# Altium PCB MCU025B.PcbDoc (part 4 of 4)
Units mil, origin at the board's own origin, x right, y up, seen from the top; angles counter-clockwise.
Board outline 2300 x 6150 mil, 6 copper layers (Top Signal, GND, Middle Signal, PWR, GND2, Bottom Signal), stack 61.64 mil thick; 237 components, 197 nets, 910 pads, 404 vias.
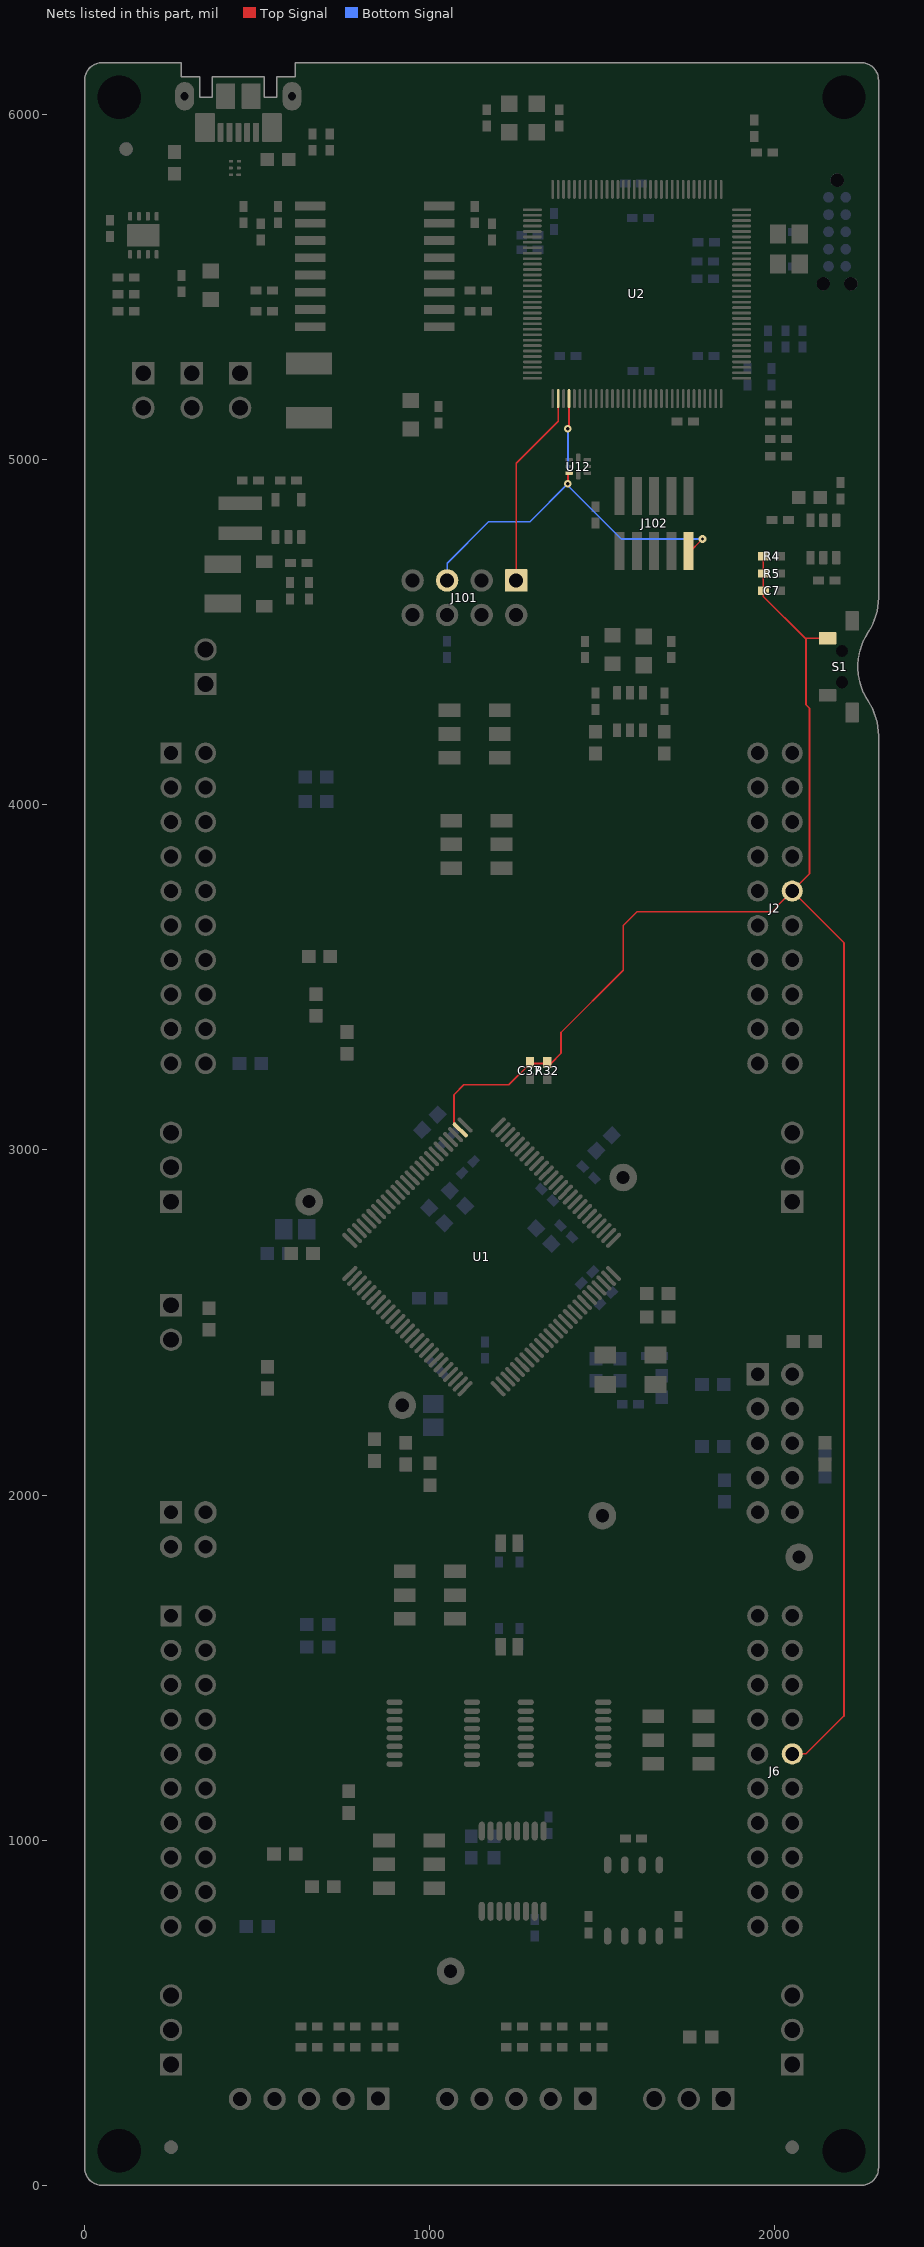
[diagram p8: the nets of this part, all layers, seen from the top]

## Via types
v1: diameter 22, hole 10, Top Signal to Bottom Signal, tented both sides, 400 vias
v2: diameter 19.68, hole 7.87, Top Signal to Bottom Signal, 4 vias

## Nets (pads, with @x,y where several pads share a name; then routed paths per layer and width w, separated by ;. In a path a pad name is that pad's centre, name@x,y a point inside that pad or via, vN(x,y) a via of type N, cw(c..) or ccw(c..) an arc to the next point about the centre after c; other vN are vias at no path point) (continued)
XDS_TMS_SWDIO: J101.5 J102.2 U2.36 U12.7 | length 1289.5
  Top Signal w5: v1(1400,4930) U12.7@1400,4960 ; v1(1400,5090) 1403.15,5093.15 U2.36@1403.15,5176.85 ; U12.7@1403.43,4960 U12.7@1403.43,4960.31 ; J102.2@1750,4730 v1(1790,4770)
  Bottom Signal w5: J101.5@1050,4650 1050,4700 1170,4820 1290,4820 v1(1400,4930) ; v1(1400,5090) v1(1400,4930) ; v1(1790,4770) 1555,4770 1400,4925 v1(1400,4930)
XDS_TXD: J101.1 U2.34 | length 577.2
  Top Signal w5: J101.1@1250,4650 1250,4990 1371.65,5111.65 U2.34@1371.65,5176.85
XRSn: C7.1 C37.2 J2.16 J6.16 R4.1 R5.2 R32.1 S1.4 U1.2 | length 5190.1
  Top Signal w5: U1.2@1088.06,3058.17 1070,3076.23 1070,3160 1098.5,3188.5 1228.5,3188.5 1290,3250 1350,3250 1380,3280 1380,3340 1560,3520 1560,3650 1600,3690 1990,3690 J2.16@2050,3750 ; C7.1@1966.38,4620 1966.38,4603.62 2087.32,4482.68 S1.4@2152.44,4482.68 ; C7.1@1966.38,4626.38 R5.2@1966.38,4670 ; R5.2@1966.38,4673.62 R4.1@1966.38,4720 ; J6.16@2050,1250 2090,1250 2200,1360 2200,3600 J2.16@2050,3750 ; 2090,4480 2090,4290 2100,4280 2100,3800 J2.16@2050,3750
pads on no net: FID1.1 FID2.1 FID3.1 FID4.1 FID5.1 FID6.1 J1.5 J2.17 J2.18 J5.9 J5.10 J6.17 J6.18 J10.7 J10.MH1 J10.MH2 J10.MH3 J11.9 J102.7 M1.0 M2.0 M3.0 M4.0 M5.0 M6.0 M7.0 M8.0 M9.0 MH1.1 MH2.1 MH3.1 MH4.1 S1. U1.43 U1.48 U1.49 U2.1 U2.2 U2.5 U2.6 U2.11 U2.12 U2.13 U2.14 U2.15 U2.18 U2.19 U2.20 U2.21 U2.22 U2.23 U2.24 U2.25 U2.27 U2.29 U2.30 U2.31 U2.32 U2.41 U2.42 U2.43 U2.44 U2.45 U2.46 U2.49 U2.50 U2.53 U2.54 U2.56 U2.57 U2.65 U2.67 U2.71 U2.72 U2.73 U2.74 U2.75 U2.76 U2.77 U2.78 U2.81 U2.82 U2.83 U2.84 U2.85 U2.86 U2.91 U2.92 U2.95 U2.102 U2.103 U2.104 U2.105 U2.106 U2.107 U2.108 U2.109 U2.110 U2.111 U2.112 U2.116 U2.117 U2.118 U2.119 U2.120 U2.121 U2.123 U2.124 U2.125 U2.126 U2.127 U2.128 U12.1 U101.7 U101.9@145.2,5650 U101.9@194.8,5650

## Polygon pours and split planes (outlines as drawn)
GND on GND "GND_GND_P018" (solid, remove dead copper, pour order 18): 865,6150 2300,6150 2300,0 0,0 0,5175 745,5175 865,5295
USB_GND on GND "GND_USB_GND_P000" (solid, remove dead copper, pour order 0): 0,5225 725,5225 815,5315 815,6150 0,6150
NetR23_1 on GND "GND_NETR23_1_P017" (solid, remove dead copper, pour order 17): 560,3300 600,3260 600,3030 860,2770 970,2880 970,2900 810,3060 810,3610 760,3660 760,4090 740,4110 580,4110 560,4090 560,3660 500,3600 320,3600 300,3580 300,3330 330,3300
NetR24_1 on GND "GND_NETR24_1_P016" (solid, remove dead copper, pour order 16): 580,1320 580,1120 560,1100 320,1100 300,1080 300,1030 300,826.67 322.86,800 700,800 800,900 800,1100 800,2450 900,2550 900,2560 820,2640 780,2640 592.5,2452.5 580,2440 580,1780
VDDA on PWR "PWR_VDDA_P014" (solid, remove dead copper, pour order 14): 977.73,3086.71 974.44,3090 869.17,3090.86 620,2850 620,2670 975,2315 1060,2400 1060,2690 1130,2760 1130,2900 1080,2950 1080,2980 1050,3020
VDD on PWR "PWR_VDD_P012" (solid, remove dead copper, pour order 12): 1555,2585 1555,2540 1530,2515 1485,2515 1270,2300 1160,2300 1111.41,2341.65 1110,2343.06 1110,2380 1170,2440 1170,2470 1260,2560 1400,2560 1470,2630 1470,2770 1190,3050 1140,3050 1080,2990 990,3080 990,3100 1040,3150 1340,3150 1580,2910 1580,2610
VDDIO on PWR "PWR_VDDIO_P010" (solid, remove dead copper, pour order 10): 870,2230 890,2210 1070,2210 1130,2270 1130,2400 1180,2440 1180,2470 1260,2550 1400,2550 1480,2630 1480,2770 1190,3060 1140,3060 1070,2990 1070,2940 1110,2900 1110,2750 1100,2750 1050,2700 1050,2410 950,2310 880,2310 870,2300
USB_VBUS on PWR "PWR_USB_VBUS_P002" (solid, remove dead copper, pour order 2): 0,6150 815,6150 815,5315 725,5225 0,5225
+3V3 on PWR "PWR_+3V3_P022" (solid, remove dead copper, pour order 22): 2300,6150 865,6150 865,5295 745,5175 0,5175 0,110 -10,100 2300,100
NetC59_1 on PWR "PWR_NETC59_1_P021" (solid, remove dead copper, pour order 21): 1840,5615 1665,5790 1645,5810 1560,5810 1550,5810 1510,5770 1510,5720 1720,5510 1880,5510 1910,5540 1910,5595 1890,5615
NetC106_2 on Top Signal "TOP_SIGNAL_NETC106_2_P030" (solid, remove dead copper, pour order 30): 730,5660 730,5505 485,5505 460,5530 460,5660
USB_VCC on Top Signal "TOP_SIGNAL_USB_VCC_P028" (solid, remove dead copper, pour order 28): 220,5220 250,5250 250,5385 325,5460 325,5715 240,5800 110,5800 50,5740 50,5280 110,5220
+3V3 on Top Signal "TOP_SIGNAL_+3V3_P027" (solid, remove dead copper, pour order 27): 480,4960 480,4930 460,4910 380,4910 380,4900 370,4890 370,4840 560,4840 590,4870 590,4960
NetD1_2 on Top Signal "TOP_SIGNAL_NETD1_2_P026" (solid, remove dead copper, pour order 26): 370,4830 550,4830 560,4820 560,4670 550,4660 460,4660 370,4750
NetC3_2 on Top Signal "TOP_SIGNAL_NETC3_2_P025" (solid, remove dead copper, pour order 25): 680,4730 660,4750 660,4755 660,4790 650,4800 605,4800 605,4705 560,4671.25 560,4630 680,4630
NetC3_1 on Top Signal "TOP_SIGNAL_NETC3_1_P024" (solid, remove dead copper, pour order 24): 325,4625 660,4625 660,4530 550,4530 420,4400 300,4400 280,4420 280,4580
+5V0 on Bottom Signal "BOTTOM_SIGNAL_+5V0_P020" (solid, remove dead copper, pour order 20): 865,6150 865,5295 745,5175 0,5175 0,0 1550,0 1550,850 1490,900 500,900 400,1000 400,4990 470,5060 800,5060 1000,5260 1000,5900 1100,6000 2000,6000 2050,6050 2050,6150
GND on GND2 "GND2_GND_P029" (solid, remove dead copper, pour order 29): 865,6160 865,5295 745,5175 -20,5175 -20,0 2320,0 2320,6160

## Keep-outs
Keep-Out Layer:
  text ".Layer_Name" at 577,-858.49 h60

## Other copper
Top Signal:
  text ".Layer_Name" at 577,-858.49 h60
GND:
  text ".Layer_Name" at 580,-860 h60
PWR:
  text ".Layer_Name" at 580,-860 h60
Middle Signal:
  text ".Layer_Name" at 580,-860 h60
GND2:
  text ".Layer_Name" at 580,-860 h60
Bottom Signal:
  text ".Layer_Name" at 577,-858.49 h60

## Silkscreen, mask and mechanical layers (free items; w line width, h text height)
Top Overlay:
  drawing of 9484 lines, arcs and shapes, not listed
  text "+3V3" at 110,5050 h30
  text "+5V0" at 250,5050 h30
  text "GND" at 410,5050 h30
  text "XDS110 Out" at 1520,4990 h30
  text "TCK" at 940,4480 h30 r270
  text "TMS" at 1040,4480 h30 r270
  text "TXD<<" at 1140,4480 h30 r270
  text "RXD>>" at 1240,4480 h30 r270
  text "XRSn" at 1980,4365 h72.83
  text "+5V0 / From Boost" at 420,4300 h30
  text "28/29" at 865.03,4260 h30
  text "UART / SELECT" at 1245,4180 h30
  text "35/37" at 865.03,4130 h30
  text "40" at 1830,4130 h30
  text "39" at 1830,4035 h30
  text "2" at 150,4030 h30
  text "19" at 2120,4030 h30
  text "BP" at 955,3940 h30
  text "38" at 1830,3935 h30
  text "3" at 150,3930 h30
  text "23" at 420,3930 h30
  text "18" at 2120,3930 h30
  text "28/29 / ROUTE" at 1255,3860 h30
  text "4" at 150,3830 h30
  text "24" at 420,3830 h30
  text "37" at 1830,3830 h30
  text "17" at 2120,3830 h30
  text "UART" at 895.02,3800 h30
  text "5" at 150,3730 h30
  text "25" at 420,3730 h30
  text "36" at 1830,3730 h30
  text "16" at 2120,3730 h30
  text "6" at 150,3630 h30
  text "26" at 420,3630 h30
  text "35" at 1830,3630 h30
  text "15" at 2120,3630 h30
  text "7" at 150,3530 h30
  text "27" at 420,3530 h30
  text "34" at 1830,3530 h30
  text "14" at 2120,3530 h30
  text "LAUNCHXL-F280049C" at 825,3450 h50
  text "8" at 150,3430 h30
  text "28" at 420,3430 h30
  text "33" at 1830,3430 h30
  text "13" at 2120,3430 h30
  text "9" at 150,3330 h30
  text "29" at 420,3330 h30
  text "32" at 1830,3330 h30
  text "12" at 2120,3330 h30
  text "30" at 420,3240 h30
  text "10" at 130,3230 h30
  text "31" at 1830,3230 h30
  text "11" at 2120,3230 h30
  text "VDD" at 1620,2900 h30
  text "VDDA" at 480,2840 h30
  text "VREFHI" at 20,2530 h30
  text "FSI" at 1915,2405 h30
  text "RXCLK" at 1719.98,2325 h30
  text "TXCLK" at 2109,2325 h30
  text "VDDIO" at 720,2240 h30
  text "TXD0" at 2176,2130 h30
  text "RXD0" at 1720,2100 h30
  text "RXD1" at 1765,2025 h30
  text "TXD1" at 2179,2025 h30
  text "+3V3" at 1560,1920 h30
  text "24" at 1120,1875 h30
  text "32" at 1290,1875 h30
  text "+3V3 / TO / J5" at 60,1820 h30
  text "+5V0 / TO / J7" at 420,1820 h30
  text "GND" at 2135,1805 h30
  text "1" at 1335,1800 h30
  text "ALT" at 800,1770 h30
  text "BOOT" at 1330,1700 h30
  text "80" at 1830,1635 h30
  text "BP" at 820,1630 h30
  text "0" at 1335,1595 h30
  text "42" at 130,1530 h30
  text "79" at 1830,1530 h30
  text "59" at 2120,1530 h30
  text "35/37 / ROUTE" at 920,1490 h30
  text "43" at 130,1430 h30
  text "63" at 420,1430 h30
  text "78" at 1830,1430 h30
  text "58" at 2120,1430 h30
  text "ALT" at 1570,1420 h30 r270
  text "44" at 130,1330 h30
  text "64" at 420,1330 h30
  text "77" at 1830,1330 h30
  text "57" at 2120,1330 h30
  text "BP" at 1570,1235 h30 r270
  text "45" at 130,1230 h30
  text "65" at 420,1230 h30
  text "76" at 1830,1230 h30
  text "56" at 2120,1230 h30
  text "46" at 130,1130 h30
  text "66" at 420,1130 h30
  text "75" at 1840,1130 h30
  text "55" at 2120,1130 h30
  text "CAN / ROUTE" at 1650,1070 h30
  text "47" at 130,1030 h30
  text "67" at 420,1030 h30
  text "74" at 1840,1030 h30
  text "54" at 2120,1030 h30
  text "BP" at 770,980 h25
  text "BP" at 1060,980 h25
  text "48" at 130,930 h30
  text "68" at 420,930 h30
  text "73" at 1830,930 h30
  text "53" at 2120,930 h30
  text "Q1" at 780,915 h25
  text "Q2" at 1060,915 h25
  text "J12" at 760,840 h25
  text "J13" at 1050,840 h25
  text "49" at 130,830 h30
  text "69" at 420,830 h30
  text "72" at 1830,830 h30
  text "52" at 2120,830 h30
  text "QEP Select" at 805,775 h30
  text "50" at 130,730 h30
  text "70" at 420,730 h30
  text "71" at 1840,730 h30
  text "51" at 2120,730 h30
  text "+5V0" at 900,640 h30
  text "EQEP2" at 600,315 h30
  text "EQEP1" at 1195,315 h30
  text "CAN" at 1735,315 h30
  text "GND" at 440,180 h30 r270
  text "+5V0" at 540,180 h30 r270
  text "2I" at 640,180 h30 r270
  text "2B" at 740,180 h30 r270
  text "2A" at 840,180 h30 r270
  text "GND" at 1040,180 h30 r270
  text "+5V0" at 1140,180 h30 r270
  text "1I" at 1240,180 h30 r270
  text "1B" at 1340,180 h30 r270
  text "1A" at 1440,180 h30 r270
  text "GND" at 1630,180 h30 r270
  text "CANL" at 1730,180 h30 r270
  text "CANH" at 1830,180 h30 r270
  text ".Layer_Name" at 577,-858.49 h60
Bottom Overlay:
  drawing of 12860 lines, arcs and shapes, not listed
  text "www.ti.com/launchpad" at 1140,4705 h100
  text "LAUNCHXL-F280049C / Development Kit" at 2300,4705 h100
  text "1" at 260,4220 h30
  text "21" at 370,4220 h30
  text "J3" at 470,4220 h40
  text "J4" at 1900,4220 h40
  text "40" at 1980,4220 h30
  text "20" at 2080,4220 h30
  text "P10" at 1880,4130 h30
  text "P11" at 1880,4035 h30
  text "PGAGND" at 180,4030 h30
  text "P57" at 2200,4030 h30
  text "P08" at 1880,3935 h30
  text "NC" at 2175,3935 h30
  text "P13" at 180,3930 h30
  text "AA5" at 500,3930 h30
  text "P40" at 180,3830 h30
  text "AB0" at 500,3830 h30
  text "P09" at 1880,3830 h30
  text "NC" at 2170,3830 h30
  text "'.PRJ_Number'.PCB_Rev" at 1370,3800 h108.27
  text "NC" at 180,3730 h30
  text "AC2" at 500,3730 h30
  text "P04" at 1880,3730 h30
  text "XRSn" at 2230,3730 h30
  text "AB3" at 180,3630 h30
  text "AB1" at 500,3630 h30
  text "P05" at 1880,3630 h30
  text "P16" at 2200,3630 h30
  text "AB2/G1I" at 570,3540 h25
  text "P56" at 180,3530 h30
  text "P58" at 1880,3530 h30
  text "P17" at 2200,3530 h30
  text "AC0/G3I" at 575,3435 h25
  text "AC4" at 180,3430 h30
  text "P30" at 1880,3430 h30
  text "P39" at 2200,3430 h30
  text "AA9/G5I" at 575,3340 h25
  text "P37" at 180,3330 h30
  text "P18" at 1880,3330 h30
  text "P23" at 2200,3330 h30
  text "P35" at 180,3230 h30
  text "P25" at 1880,3230 h30
  text "P59" at 2200,3230 h30
  text "AA1/DACB" at 640,3180 h30
  text "10" at 270,3150 h30
  text "30" at 380,3150 h30
  text "31" at 1970,3150 h30
  text "11" at 2070,3150 h30
  text "41" at 280,1720 h30
  text "61" at 370,1720 h30
  text "J7" at 470,1720 h40
  text "J8" at 1900,1720 h40
  text "80" at 1970,1720 h30
  text "60" at 2080,1720 h30
  text "P00" at 1880,1635 h30
  text "PGAGND" at 175,1530 h30
  text "P01" at 1880,1530 h30
  text "P27" at 2200,1530 h30
  text "P28" at 175,1430 h30
  text "AA6" at 500,1430 h30
  text "P06" at 1875,1430 h30
  text "NC" at 2170,1430 h30
  text "P29" at 175,1330 h30
  text "AB6" at 500,1330 h30
  text "NC" at 2170,1330 h30
  text "P07" at 1880,1325 h30
  text "AB4/G4O" at 180,1240 h25
  text "AC14" at 525,1230 h30
  text "P02" at 1880,1230 h30
  text "XRSn" at 2230,1230 h30
  text "AA4/G2O" at 180,1135 h25
  text "AC1" at 490,1130 h30
  text "P03" at 1880,1130 h30
  text "P24" at 2200,1130 h30
  text "AC3/G4I" at 575,1035 h25
  text "P22" at 180,1030 h30
  text "P26" at 1880,1030 h30
  text "P31" at 2200,1030 h30
  text "AA8/G6O" at 180,935 h25
  text "P15" at 1880,930 h30
  text "P33" at 2200,930 h30
  text "AC5/G6I" at 575,895 h25
  text "AA3/G2I" at 575,835 h25
  text "NC" at 180,830 h30
  text "P14" at 1880,830 h30
  text "P34" at 2200,830 h30
  text "NC" at 180,730 h30
  text "P32" at 1880,730 h30
  text "P12" at 2200,730 h30
  text "AA0/DACA" at 650,680 h30
  text "71" at 1970,650 h30
  text "51" at 2070,650 h30
  text "50" at 270,640 h30
  text "70" at 370,640 h30
  text ".Layer_Name" at 577,-858.49 h60
Top Paste:
  text ".Layer_Name" at 577,-858.49 h60
Bottom Paste:
  text ".Layer_Name" at 577,-858.49 h60
Top Solder:
  text ".Layer_Name" at 577,-858.49 h60
  text ".Layer_Name" at 577,-858.49 h60
Bottom Solder:
  text ".Layer_Name" at 577,-858.49 h60
Drill Guide:
  text ".Layer_Name" at 577,-858.49 h60
M1 Board Outline:
  the board outline again, w10
  text ".Layer_Name" at 577,-858.49 h60
M2 Board Dimensions:
  rectangle: 125,-400 500,-275
  rectangle: 0,-275 125,-150
  lines w7: 0,-275 1000,-275 ; 125,-400 125,-150 ; 250,-400 250,-150 ; 500,-400 500,-150 ; 750,-400 750,-150 ; 0,-400 0,-150 1000,-150 1000,-400 0,-400
  text "Radius 50 mil, 4 corners" at 2406,-202 h100
  text ".Layer_Name" at 577,-858.49 h60
M3 3D STEP Top:
  text ".Layer_Name" at 577,-858.49 h60
M4 3D STEP Bottom:
  text ".Layer_Name" at 577,-858.49 h60
M5 Assembly Top:
  lines w10: -292,-930.17 6308,-930.17 ; -292,-726.83 6310,-726.83 ; -292,-523.5 -292,-1133.5 3713,-1133.5 6310,-1133.5 6310,-523.5 -291.5,-523.5 -291.5,-1133.5 1284,-1133.5 ; 2173,-1133.5 2173,-523.5 ; 3440,-726.83 3440,-523.5 ; 4280,-726.83 4280,-523.5 ; 4902,-1140 4902,-937.17
  text "Place all Shunts (9 total) as described  in Figure 1 of Test Procedure." at 140,6720 h40
  text "Ensure that all switches are placed in the proper direction with default positions as described in Figure 1 of Test Procedure" at 140,6620 h40
  text "COMPONENTS MARKED 'DNP' SHOULD NOT BE POPULATED." at 1153.5,-318.5 h60
  text "ASSEMBLY VARIANT:" at 1153,-434 h60
  text ".VariantName" at 2189,-434 h60
  text "PCB VIEWED FROM TOP SIDE" at -228.5,-655.67 h60
  text "BOARD #:" at 2248,-655.67 h60
  text ".PRJ_Number" at 2793.5,-655.67 h60
  text "REV:" at 3638,-655.67 h60
  text ".PCB_Rev" at 3929.5,-655.67 h60
  text "SVN REV:" at 4476,-655.67 h60
  text ".VersionControl_RevNumber" at 4982,-655.67 h60
  text "TID #:" at 2248,-859 h60
  text ".TID" at 2793.5,-859 h60
  text ".Layer_Name" at 580,-860 h60
  text "PLOT NAME =" at -228.5,-1064.34 h60
  text ".plot_File_Name" at 577,-1064.34 h60
  text "GENERATED    :" at 2250,-1064.34 h60
  text ".Print_Date" at 3119.5,-1064.34 h60
  text ".Print_Time" at 3848.5,-1064.34 h60
  text "TEXAS INSTRUMENTS" at 5113,-1064.34 h60
M6 Assembly Bottom:
  lines w10: -292.5,-727.33 6309.5,-727.33 ; -290.5,-930.67 6309.5,-930.67 ; 1115.5,-1140.5 1115.5,-937.67 ; 1737.5,-727.33 1737.5,-524 ; 2577.5,-727.33 2577.5,-524 ; 3844.5,-1134 3844.5,-524 ; 4733.5,-1134 6309,-1134 6309,-524 -292.5,-524 -292.5,-1134 2304.5,-1134 6309.5,-1134 6309.5,-524
  text "COMPONENTS MARKED 'DNP' SHOULD NOT BE POPULATED." at 6102,-318 h60
  text ".VariantName" at 5058,-434 h60
  text "ASSEMBLY VARIANT:" at 6097,-434 h60
  text ".VersionControl_RevNumber" at 1035.5,-656.17 h60
  text "SVN REV:" at 1541.5,-656.17 h60
  text ".PCB_Rev" at 2088,-656.17 h60
  text "REV:" at 2379.5,-656.17 h60
  text ".PRJ_Number" at 3224,-656.17 h60
  text "BOARD #:" at 3769.5,-656.17 h60
  text "PCB VIEWED FROM BOTTOM SIDE" at 6246,-656.17 h60
  text ".Layer_Name" at 580,-860 h60
  text ".TID" at 3224,-859.5 h60
  text "TID #:" at 3769.5,-859.5 h60
  text "TEXAS INSTRUMENTS" at 904.5,-1064.84 h60
  text ".Print_Time" at 2169,-1064.84 h60
  text ".Print_Date" at 2898,-1064.84 h60
  text "GENERATED    :" at 3767.5,-1064.84 h60
  text ".plot_File_Name" at 5440.5,-1064.84 h60
  text "PLOT NAME =" at 6246,-1064.84 h60
M7 LPKF Text Top:
  text ".Layer_Name" at 580,-860 h60
M8 LPKF Text Bottom:
  text ".Layer_Name" at 580,-860 h60
M9 Title Sheet:
  drawing of 57 lines, arcs and shapes, not listed
  text "1" at 739.84,8036.5 h70
  text "2" at 3235.5,8036.5 h70
  text "3" at 5724.84,8036.5 h70
  text "4" at 8231.51,8036.5 h70
  text "5" at 10730.5,8036.5 h70
  text "6" at 13235.5,8036.5 h70
  text "A" at -416.5,6893.5 h70
  text "A" at 14383.5,6893.5 h70
  text "B" at -416.5,4513.5 h70
  text "B" at 14383.5,4513.5 h70
  text "C" at -416.5,2138.5 h70
  text "C" at 14383.5,2138.5 h70
  text "PROJECT TITLE:" at 11343.5,277.5 h45
  text ".PRJ_Title" at 11393.5,144.17 h70
  text "DESIGNED FOR:" at 11343.5,-23.5 h45
  text ".PRJ_Customer" at 11393.5,-163.5 h70
  text "D" at -416.5,-231.5 h70
  text "D" at 14383.5,-231.5 h70
  text "FILE NAME:" at 11343.5,-323.5 h45
  text ".PCB_File_Name_No_Path" at 11393.5,-443.5 h70
  text "Texas Instruments (TI) and/or its licensors do not warrant the accuracy or completeness of this specification" at 6374,-605.34 h45
  text "ENGINEER:" at 11343.5,-613.5 h45
  text "LAYOUT BY:" at 12848.5,-613.5 h45
  text "or any information contained therein. TI and/or its licensors do not warrant that this design will meet" at 6329.01,-718 h45
  text ".PRJ_Engineer" at 11393.5,-768.49 h70
  text ".PCB_Layout" at 12899,-768.49 h70
  text "the specifications, will be suitable for your application or fit for any particular purpose, or will operate in" at 6329.01,-830.67 h45
  text ".Layer_Name" at 577,-858.49 h60
  text "ALTIUM DESIGNER VERSION:" at 12848.5,-923.5 h45
  text "an implementation. TI and/or its licensors do not warrant that the design is production worthy. You should" at 6329.01,-943.33 h45
  text "completely validate and test your design implementation to confirm the system functionality for your application." at 6374,-1056 h45
  text ".print_Scale" at 11393.5,-1056.83 h70
  text ".Application_BuildNumber" at 12899,-1056.83 h70
  text "1" at 739.84,-1263.5 h70
  text "2" at 3235.5,-1263.5 h70
  text "3" at 5724.84,-1263.5 h70
  text "4" at 8231.51,-1263.5 h70
  text "5" at 10730.5,-1263.5 h70
  text "6" at 13235.5,-1263.5 h70
M10 Fab Notes:
  drawing of 189 lines, arcs and shapes, not listed
  text "DESIGN INFORMATION" at 12382.02,6356.17 h60
  text "MIN. TRACK WIDTH:" at 11737.46,6224.05 h60
  text "5" at 12833.7,6224.05 h60
  text "MIL" at 12988.46,6224.05 h60
  text "MIN. CLEARANCE:" at 11737.46,6099.92 h60
  text "0.2" at 12773.7,6099.93 h60
  text "mm" at 12988.46,6099.92 h60
  text "MIN. VIA PAD SIZE:" at 11737.46,5975.8 h60
  text "24" at 12803.71,5975.8 h60
  text "MIL" at 12988.46,5975.8 h60
  text "0.05mm (2MIL)" at 12432.46,5845.9 h60
  text "MINIMUM ANNULAR RING" at 11408.23,5837.67 h60
  text "EXTERNAL" at 13140.46,5837.67 h60
  text "PER" at 11608.23,5727.55 h60
  text "IPC-D-275 CLASS 2 LEVEL C" at 11828.23,5727.54 h60
  text "MIL, HOLES" at 13316.46,5627.07 h60
  text "+/-" at 12924,5618.48 h60
  text "+/-" at 13778,5618.48 h60
  text "REGISTRATION TOLERANCES:" at 11408.23,5617.42 h60
  text "METAL" at 12608,5617.42 h60
  text "5" at 13184.2,5617.42 h60
  text "3" at 14017.2,5617.42 h60
  text "MIL" at 14133.46,5617.42 h60
  text "HOLE SIZE TOLERANCE (UNLESS OTHERWISE SPECIFIED):" at 11408.23,5519.1 h60
  text "+/-" at 13778,5516.23 h60
  text "5" at 14017.2,5515.17 h60
  text "MIL" at 14133.46,5515.17 h60
  text "MATERIAL:" at 11333.46,5377.52 h60
  text "FR-4 High Tg" at 12319.9,5249 h60
  text "X" at 12175.46,5241.01 h60
  text "FR-408" at 11754.46,5236.49 h60
  text "OTHER" at 13242.46,5236.49 h60
  text "62 MIL (1.6mm) +/-10%" at 12074.56,5093.46 h60
  text "X" at 11954.46,5091.01 h60
  text "THICKNESS:" at 11408.23,5085.24 h60
  text "OTHER" at 13359.46,5085.24 h60
  text "TOLERANCE:" at 11408.23,4946.92 h60
  text "ANSI IPC-6012 TYPE 3 CLASS 2" at 12434.48,4946.92 h60
  text "IPC-A600" at 13120,4820 h72.83
  text "OTHER +/-" at 12434.46,4802.73 h60
  text "X" at 12265,4800 h60
  text "BOW & TWIST:" at 11408.23,4657.54 h60
  text "ANSI IPC-6012 TYPE 3 CLASS 2" at 12434.48,4657.54 h60
  text "X" at 12255,4535 h60
  text "IPC-A600" at 13120,4515 h72.83
  text "OTHER +/-" at 12434.46,4510.85 h60
  text "DRILLING:" at 11333.46,4380.23 h60
  text "NC_DRILL FILES" at 13094.46,4275.04 h60
  text "REFERENCE:" at 11408.23,4271.1 h60
  text "X" at 12065.46,4271.01 h60
  text "AS SHOWN" at 12243.46,4271.1 h60
  text "X" at 12966.46,4271.1 h60
  text "OTHER" at 13392.46,4128.85 h60
  text "PTH COPPER THICKNESS:" at 11407.91,4125.32 h60
  text "X" at 12547.14,4125.32 h60
  text "20-30 um" at 12675.14,4125.32 h60
  text "BOARD FINISH:" at 11333.46,3977.73 h60
  text "SILKSCREEN:" at 11488.68,3867.6 h60
  text "X" at 12446.46,3867.6 h60
  text "TOP" at 12563.46,3867.6 h60
  text "X" at 12956.46,3867.6 h60
  text "BOTTOM" at 13074.46,3867.6 h60
  text "SILKSCREEN COLOR:" at 11488.68,3712.41 h60
  text "X" at 12445.46,3712.41 h60
  text "WHITE" at 12563.46,3712.41 h60
  text "OTHER" at 13074.46,3712.41 h60
  text "RED" at 13712,3579 h80
  text "GREEN" at 12694.46,3568.96 h60
  text "OTHER" at 13312.46,3568.96 h60
  text "X" at 13166,3565 h60
  text "SOLDER RESIST COLOR:" at 11488.68,3562.1 h60
  text "MATTE" at 12694.46,3414.71 h60
  text "SEMI-GLOSS" at 13312,3414.07 h60
  text "IMMERSION GOLD (ENIG)" at 12394.46,3241.94 h60
  text "ENEPIG" at 13732,3234.72 h60
  text "SURFACE FINISH:" at 11333.46,3233.72 h60
  text "IMM. TIN/SILVER OR EQUIV" at 11663,3096.4 h60
  text "X" at 11515,3095 h60
  text "OTHER" at 13094.46,3092.47 h60
  text "ARRAY/PANEL:" at 11333.46,2937.09 h60
  text "CUT AND TRIM PER M1 BOARD OUTLINE" at 12394.46,2928.87 h60
  text "X" at 12216,2927 h60
  text "N.C. ROUTE" at 12394.46,2792.9 h60
  text "V. SCORE" at 13260.46,2792.9 h60
  text "CERTIFICATION:" at 11333.46,2663.77 h60
  text "MATERIALS AND WORKMANSHIP FOR ALL PCBS" at 12058.46,2663.77 h60
  text "TO MEET OR EXCEED THE REQUIREMENTS OF:" at 12058.46,2569.71 h60
  text "X" at 11695.97,2441.08 h60
  text "ANSI IPC-A-600F CLASS ->" at 11823.96,2441.08 h60
  text "2" at 13581.96,2441.08 h60
  text "1" at 13266.96,2439.58 h60
  text "3" at 13935.96,2439.58 h60
  text "X" at 12507.97,2293.39 h60
  text "RoHS" at 12635.96,2293.39 h60
  text "OTHER" at 13280.36,2293.39 h60
  text "PER ORDER" at 13677.42,2293.39 h60
  text "ALL BOARDS MUST MEET OR EXCEED UL94-V0 REQUIREMENTS." at 11361,2139.57 h60
  text "PCB MUST BEAR THE UL94V-0 UL REGISTERED MATERIAL ID NUMBER" at 11361,2023.5 h60
  text "ADDITIONAL REQUIREMENTS:" at 11333.46,1854.08 h60
  text "MICROSECTION:" at 11408.23,1746.95 h60
  text "YES" at 12313.96,1746.95 h60
  text "X" at 12592,1605 h60
  text "REQUIRED" at 13175.46,1602.62 h60
  text "BARE BOARD ELEC. TEST:" at 11408.23,1599.76 h60
  text "NONE" at 12713.96,1599.76 h60
  text "PER ORDER" at 13767.46,1599.76 h60
  text "XX MIL VIAS REQUIRE NON-CONDUCTIVE FILL AND PLANARIZE" at 11576.38,1394.82 h59
  text "XX MIL VIAS REQUIRE CONDUCTIVE FILL AND PLANARIZE" at 11584.38,1290.84 h60
  text "OUTER XX MIL VIAS REQUIRE 50 OHM SINGLE-ENDED IMPEDANCE" at 11583.39,1127.46 h58
  text "LAYER 2 & 3 (INNER LAYERS) XX MIL WIDE, XX MIL SPACE / TRACES REQUIRE 100 OHM DIFFERENTIAL IMPEDANCE" at 11575.39,891.74 h60
  text ".Layer_Name" at 577,-858.49 h60
M11 Gerber Information:
  lines w10: -292,-930.17 6308,-930.17 ; -292,-726.83 6310,-726.83 ; -292,-523.5 -292,-1133.5 3713,-1133.5 6310,-1133.5 6310,-523.5 -291.5,-523.5 -291.5,-1133.5 1284,-1133.5 ; 2173,-1133.5 2173,-523.5 ; 3440,-726.83 3440,-523.5 ; 4280,-726.83 4280,-523.5 ; 4902,-1140 4902,-937.17
  text "ALL ARTWORK VIEWED FROM TOP SIDE" at -228.5,-655.67 h60
  text "BOARD #:" at 2248,-655.67 h60
  text ".PRJ_Number" at 2793.5,-655.67 h60
  text "REV:" at 3638,-655.67 h60
  text ".PCB_Rev" at 3929.5,-655.67 h60
  text "SVN REV:" at 4476,-655.67 h60
  text ".VersionControl_RevNumber" at 4982,-655.67 h60
  text "LAYER NAME =" at -228.5,-858.49 h60
  text "TID #:" at 2248,-859 h60
  text ".TID" at 2793.5,-859 h60
  text ".Layer_Name" at 580,-860 h60
  text "PLOT NAME =" at -228.5,-1064.34 h60
  text ".plot_File_Name" at 577,-1064.34 h60
  text "GENERATED    :" at 2250,-1064.34 h60
  text ".Print_Date" at 3119.5,-1064.34 h60
  text ".Print_Time" at 3848.5,-1064.34 h60
  text "TEXAS INSTRUMENTS" at 5113,-1064.34 h60
M12 Stackup:
  drawing of 399 lines, arcs and shapes, not listed
  text "Layer" at 6505.58,7087.5 h60
  text "Name" at 6915.49,7087.5 h60
  text "Material" at 7845.23,7087.5 h60
  text "Thickness" at 8705,7087.5 h60
  text "Constant" at 9354.84,7087.5 h60
  text "Board Layer Stack" at 9924.7,7087.5 h60
  text "1" at 6505.58,6967.5 h60
  text "Top Overlay" at 6915.49,6967.5 h60
  text "2" at 6505.58,6847.5 h60
  text "Top Solder" at 6915.49,6847.5 h60
  text "Solder Resist" at 7845.23,6847.5 h60
  text "0.40mil" at 8705,6847.5 h60
  text "3.5" at 9354.84,6847.5 h60
  text "3" at 6505.58,6727.5 h60
  text "Top Signal" at 6915.49,6727.5 h60
  text "Copper" at 7845.23,6727.5 h60
  text "1.40mil" at 8705,6727.5 h60
  text "4" at 6505.58,6607.5 h60
  text "Dielectric 1" at 6915.49,6607.5 h60
  text "FR-4" at 7845.23,6607.5 h60
  text "6.25mil" at 8705,6607.5 h60
  text "4.2" at 9354.84,6607.5 h60
  text "5" at 6505.58,6487.5 h60
  text "GND" at 6915.49,6487.5 h60
  text "Copper" at 7845.23,6487.5 h60
  text "1.40mil" at 8705,6487.5 h60
  text "6" at 6505.58,6367.5 h60
  text "Dielectric 2" at 6915.49,6367.5 h60
  text "FR-4" at 7845.23,6367.5 h60
  text "16.10mil" at 8705,6367.5 h60
  text "4.2" at 9354.84,6367.5 h60
  text "7" at 6505.58,6247.5 h60
  text "Middle Signal" at 6915.49,6247.5 h60
  text "Copper" at 7845.23,6247.5 h60
  text "1.40mil" at 8705,6247.5 h60
  text "8" at 6505.58,6127.5 h60
  text "Dielectric 3" at 6915.49,6127.5 h60
  text "FR-4" at 7845.23,6127.5 h60
  text "8.54mil" at 8705,6127.5 h60
  text "4.2" at 9354.84,6127.5 h60
  text "9" at 6505.58,6007.5 h60
  text "PWR" at 6915.49,6007.5 h60
  text "Copper" at 7845.23,6007.5 h60
  text "1.40mil" at 8705,6007.5 h60
  text "10" at 6505.58,5887.5 h60
  text "Dielectric 4" at 6915.49,5887.5 h60
  text "FR-4" at 7845.23,5887.5 h60
  text "16.10mil" at 8705,5887.5 h60
  text "4.2" at 9354.84,5887.5 h60
  text "11" at 6505.58,5767.5 h60
  text "GND2" at 6915.49,5767.5 h60
  text "Copper" at 7845.23,5767.5 h60
  text "1.40mil" at 8705,5767.5 h60
  text "12" at 6505.58,5647.5 h60
  text "Dielectric 5" at 6915.49,5647.5 h60
  text "FR-4" at 7845.23,5647.5 h60
  text "6.25mil" at 8705,5647.5 h60
  text "4.2" at 9354.84,5647.5 h60
  text "13" at 6505.58,5527.5 h60
  text "Bottom Signal" at 6915.49,5527.5 h60
  text "Copper" at 7845.23,5527.5 h60
  text "1.40mil" at 8705,5527.5 h60
  text "14" at 6505.58,5407.5 h60
  text "Bottom Solder" at 6915.49,5407.5 h60
  text "Solder Resist" at 7845.23,5407.5 h60
  text "0.40mil" at 8705,5407.5 h60
  text "3.5" at 9354.84,5407.5 h60
  text "15" at 6505.58,5287.5 h60
  text "Bottom Overlay" at 6915.49,5287.5 h60
  text "Use Standard 6 Layer Stackup" at 7220,5250 h250
  text ".Layer_Name" at 577,-858.49 h60
M13 Component Bodies Top:
  text ".Layer_Name" at 577,-858.49 h60
M14 Component Bodies Bottom:
  text ".Layer_Name" at 577,-858.49 h60
M15 Courtyards Top:
  text ".Layer_Name" at 577,-858.49 h60
M16 Courtyards Bottom:
  text ".Layer_Name" at 577,-858.49 h60
Drill Drawing:
  circle w10: c5363.73,3361.9 r16.58
  circle w10: c5363.73,3361.9 r27.63
  circle w10: c5363.73,2740.23 r27.63
  lines w10: 5336.1,2146.18 5391.36,2146.18 5363.73,2090.92 5336.1,2146.18 ; 5336.1,2229.07 5349.91,2229.07 5363.73,2215.25 5377.54,2229.07 5391.36,2229.07 5377.54,2242.89 5391.36,2256.7 5377.54,2256.7 5363.73,2270.52 5349.91,2256.7 5336.1,2256.7 5349.91,2242.89 5336.1,2229.07 ; 5336.1,2367.22 5363.73,2339.59 5391.36,2367.22 5363.73,2394.85 5336.1,2367.22 ; 5336.1,2477.74 5349.91,2477.74 5349.91,2463.93 5377.54,2463.93 5377.54,2477.74 5391.36,2477.74 5391.36,2505.37 5377.54,2505.37 5377.54,2519.19 5349.91,2519.19 5349.91,2505.37 5336.1,2505.37 5336.1,2477.74 ; 5336.1,2588.26 5363.73,2602.08 5391.36,2588.26 5377.54,2615.89 5391.36,2643.52 5363.73,2629.71 5336.1,2643.52 5349.91,2615.89 5336.1,2588.26 ; 5336.1,2892.19 5391.36,2892.19 5363.73,2836.93 5336.1,2892.19 ; 5336.1,2961.27 5391.36,2961.27 5391.36,3016.53 5336.1,3016.53 5336.1,2961.27 ; 5336.1,3085.6 5336.1,3099.42 5349.91,3113.23 5336.1,3127.05 5336.1,3140.86 5349.91,3140.86 5363.73,3127.05 5377.54,3140.86 5391.36,3140.86 5391.36,3127.05 5377.54,3113.23 5391.36,3099.42 5391.36,3085.6 5377.54,3085.6 5363.73,3099.42 5349.91,3085.6 5336.1,3085.6 ; 5336.1,3209.94 5391.36,3209.94 5391.36,3265.2 5336.1,3265.2 5336.1,3209.94 ; 5347.15,2881.14 5380.3,2881.14 5363.73,2847.98 5347.15,2881.14 ; 5347.15,2972.32 5380.3,2972.32 5380.3,3005.47 5347.15,3005.47 5347.15,2972.32
  lines w12: 5286,2053.62 8547.18,2053.62 ; 5286,3421.31 8547.18,3421.31 ; 5623.75,1929.28 5623.75,3545.64 ; 5955.56,1929.28 5955.56,3545.64 ; 6591.66,1929.28 6591.66,3545.64 ; 6850.66,1929.28 6850.66,3545.64 ; 7225.64,1929.28 7225.64,3545.64 ; 7980.98,1929.28 7980.98,3545.64 ; 5286,1929.28 8547.18,1929.28 8547.18,3545.64 5286,3545.64 5286,1929.28
  text "Symbol" at 5360.6,3458.61 h72
  text "Quantity" at 5661.05,3458.61 h72
  text "Finished Hole Size" at 5992.86,3458.61 h72
  text "Plated" at 6628.96,3458.61 h72
  text "Hole Type" at 6887.96,3458.61 h72
  text "Drill Layer Pair" at 7262.94,3458.61 h72
  text "Hole Tolerance" at 8018.28,3458.61 h72
  text "2" at 5661.05,3334.27 h60
  text "35.43mil (0.900mm)" at 5992.86,3334.27 h60
  text "NPTH" at 6628.96,3334.27 h60
  text "Round" at 6887.96,3334.27 h60
  text "Top Signal - Bottom Signal" at 7262.94,3334.27 h60
  text "3" at 5661.05,3209.94 h60
  text "39.00mil (0.991mm)" at 5992.86,3209.94 h60
  text "NPTH" at 6628.96,3209.94 h60
  text "Round" at 6887.96,3209.94 h60
  text "Top Signal - Bottom Signal" at 7262.94,3209.94 h60
  text "4" at 5661.05,3085.6 h60
  text "125.00mil (3.175mm)" at 5992.86,3085.6 h60
  text "NPTH" at 6628.96,3085.6 h60
  text "Round" at 6887.96,3085.6 h60
  text "Top Signal - Bottom Signal" at 7262.94,3085.6 h60
  text "4" at 5661.05,2961.27 h60
  text "7.87mil (0.200mm)" at 5992.86,2961.27 h60
  text "PTH" at 6628.96,2961.27 h60
  text "Round" at 6887.96,2961.27 h60
  text "Top Signal - Bottom Signal" at 7262.94,2961.27 h60
  text "3" at 5661.05,2836.93 h60
  text "10.00mil (0.254mm)" at 5992.86,2836.93 h60
  text "PTH" at 6628.96,2836.93 h60
  text "Round" at 6887.96,2836.93 h60
  text "Top Signal - Bottom Signal" at 7262.94,2836.93 h60
  text "397" at 5661.05,2712.6 h60
  text "10.00mil (0.254mm)" at 5992.86,2712.6 h60
  text "PTH" at 6628.96,2712.6 h60
  text "Round" at 6887.96,2712.6 h60
  text "Top Signal - Bottom Signal" at 7262.94,2712.6 h60
  text "+/-5.00mil" at 8018.28,2712.6 h60
  text "6" at 5661.05,2588.26 h60
  text "37.99mil (0.965mm)" at 5992.86,2588.26 h60
  text "PTH" at 6628.96,2588.26 h60
  text "Round" at 6887.96,2588.26 h60
  text "Top Signal - Bottom Signal" at 7262.94,2588.26 h60
  text "32" at 5661.05,2463.93 h60
  text "40.00mil (1.016mm)" at 5992.86,2463.93 h60
  text "PTH" at 6628.96,2463.93 h60
  text "Round" at 6887.96,2463.93 h60
  text "Top Signal - Bottom Signal" at 7262.94,2463.93 h60
  text "80" at 5661.05,2339.59 h60
  text "40.16mil (1.020mm)" at 5992.86,2339.59 h60
  text "PTH" at 6628.96,2339.59 h60
  text "Round" at 6887.96,2339.59 h60
  text "Top Signal - Bottom Signal" at 7262.94,2339.59 h60
  text "25" at 5661.05,2215.25 h60
  text "45.28mil (1.150mm)" at 5992.86,2215.25 h60
  text "PTH" at 6628.96,2215.25 h60
  text "Round" at 6887.96,2215.25 h60
  text "Top Signal - Bottom Signal" at 7262.94,2215.25 h60
  text "2" at 5661.05,2090.92 h60
  text "23.62mil (0.600mm)" at 5992.86,2090.92 h60
  text "PTH" at 6628.96,2090.92 h60
  text "Slot" at 6887.96,2090.92 h60
  text "Top Signal - Bottom Signal" at 7262.94,2090.92 h60
  text "558 Total" at 5661.05,1966.58 h60
  text "Slot definitions :" at 5360.6,1879.55 h60
  text "Routed Path Length" at 5811.08,1879.55 h60
  text "= Calculated from tool start centre position to tool end centre position." at 6350.63,1879.55 h60
  text "Hole Length" at 5811.08,1829.82 h60
  text "= Routed Path Length + Tool Size = Slot length as defined in the PCB layout" at 6150.89,1829.82 h60
  text ".Layer_Name" at 577,-858.49 h60
M17 Embedded Cavity:
  text ".Layer_Name" at 577,-858.49 h60
M18 Embedded Assembly:
  text ".Layer_Name" at 577,-858.49 h60
M19 Embedded Keepout:
  text ".Layer_Name" at 577,-858.49 h60

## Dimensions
2118.33,4200 to 2438,4202 on M2 Board Dimensions
2118.33,4600 to 2461,4585 on M2 Board Dimensions
2421.67,4400 to 2400,4400 on M2 Board Dimensions
2250,50 to 2375,-65 on M2 Board Dimensions
0,0 to 2300,0 on M2 Board Dimensions
0,0 to 0,6150 on M2 Board Dimensions
0,-400 to 1000,-400 on M2 Board Dimensions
